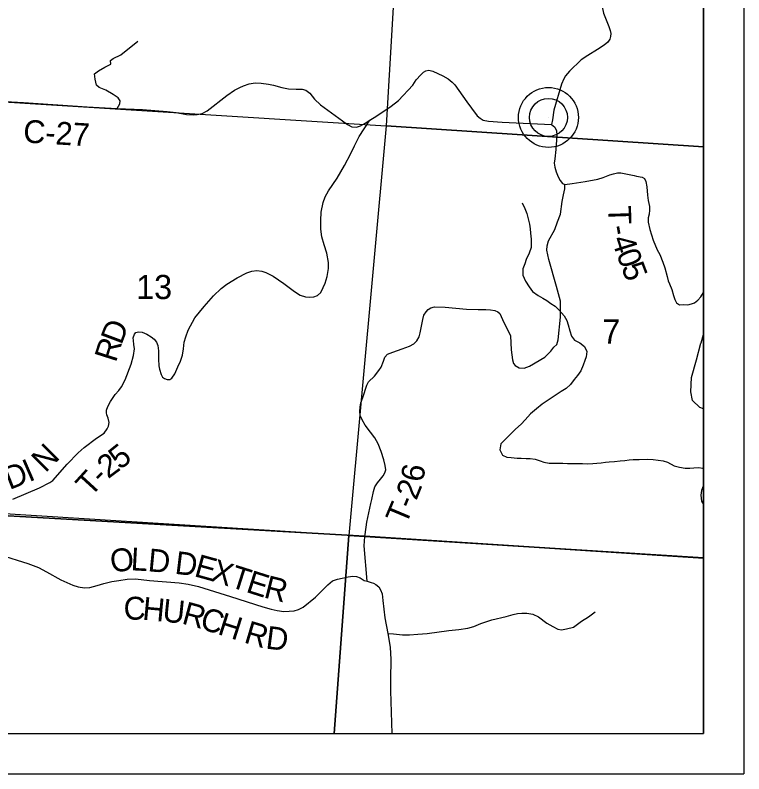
# Model space of a CAD drawing. Extents: x 0 to 34, y 0 to 22.
# Drawn here: x 7.19 to 9, y 14 to 15.883 of the extents above; entities that cross this region are included whole.
import ezdxf

# ---------------------------------------------------------------- set-up
doc = ezdxf.new("R2010")
doc.units = 0
for name, color, linetype in [('GM_X_Corporation', 7, 'Continuous'), ('GM_X_County_Road', 7, 'Continuous'), ('GM_X_County_Road_Text', 7, 'Continuous'), ('GM_X_Major_River', 7, 'Continuous'), ('GM_X_Section_Text', 7, 'Continuous'), ('GM_X_Township_Road', 7, 'Continuous'), ('GM_X_Township_Road_Text', 7, 'Continuous'), ('GM_X_Township_Text', 7, 'Continuous'), ('GM_X_Unincorporated', 7, 'Continuous'), ('GM_X_Unincorporated_Location', 7, 'Continuous'), ('SH_Data', 7, 'Continuous')]:
    doc.layers.add(name, color=color, linetype=linetype)

msp = doc.modelspace()

# ---------------------------------------------------------------- linework, layer by layer
at = {"layer": 'GM_X_Corporation'}
for points in [[(8.9, 15.5562), (8.9, 16.5775), (8.644, 16.594), (8.1703, 16.6232), (8.1663, 16.5368), (8.1403, 16.1), (8.1117, 15.6084)], [(7.097, 15.6707), (7.1079, 15.6712), (8.1117, 15.6084), (8.0192, 14.5919), (7.0183, 14.6543)], [(8.9, 14.5358), (8.9, 15.5562), (8.1117, 15.6084), (8.0192, 14.5919)], [(3.9197, 14.1), (8.9, 14.1), (8.9, 14.5351), (8.0587, 14.59), (7.0121, 14.6499), (6.0453, 14.7107), (5.2037, 14.7544), (4.6148, 14.7919), (3.9742, 14.8327)], [(6.9776, 14.1), (7.9827, 14.1), (8.0192, 14.5919), (7.0183, 14.6543)], [(7.9827, 14.1), (8.9, 14.1), (8.9, 14.5358), (8.0192, 14.5919)]]:
    msp.add_lwpolyline(points, close=True, dxfattribs=at)
at = {"layer": 'GM_X_County_Road'}
for points in [[(8.6428, 16.0121), (8.6415, 15.9944), (8.6407, 15.9598), (8.6432, 15.9369), (8.6456, 15.9158), (8.6518, 15.8883), (8.6643, 15.8553), (8.6681, 15.8451), (8.6695, 15.8379), (8.6687, 15.8305), (8.6671, 15.8238), (8.6624, 15.8161), (8.6534, 15.8085), (8.6369, 15.7985), (8.6126, 15.7832), (8.5958, 15.7721), (8.567, 15.7446), (8.557, 15.7324), (8.5528, 15.7256), (8.547, 15.7123), (8.5284, 15.6477), (8.5247, 15.6238), (8.522, 15.612)], [(7.1364, 15.6707), (7.2111, 15.6666), (7.3687, 15.6558), (7.443, 15.6516), (7.5067, 15.6488), (7.5672, 15.6439), (7.5896, 15.6413), (7.6152, 15.6371), (7.6318, 15.6357), (7.6423, 15.6366), (7.6542, 15.639), (7.6673, 15.6462), (7.7161, 15.6842), (7.7345, 15.6969), (7.7481, 15.7034), (7.7572, 15.7081), (7.771, 15.7125), (7.7861, 15.7151), (7.8013, 15.7144), (7.8195, 15.712), (7.8314, 15.7092), (7.852, 15.7041), (7.8686, 15.7004), (7.8879, 15.6999), (7.9031, 15.6999), (7.9122, 15.6973), (7.9218, 15.6899), (7.9337, 15.6744), (7.9483, 15.6605), (8.0035, 15.621), (8.0154, 15.6119), (8.0264, 15.6065), (8.038, 15.6053), (8.0476, 15.6084), (8.0598, 15.6149), (8.0707, 15.6224), (8.088, 15.6338), (8.1244, 15.6572), (8.1419, 15.6712), (8.1779, 15.7097), (8.1865, 15.7226), (8.1976, 15.7354), (8.2042, 15.7419), (8.21, 15.7453), (8.2175, 15.7464), (8.2274, 15.7442), (8.252, 15.7324), (8.2657, 15.7249), (8.2755, 15.717), (8.2824, 15.71), (8.3117, 15.668), (8.3233, 15.6526), (8.338, 15.6338), (8.3451, 15.6278), (8.3526, 15.6224), (8.3656, 15.6198), (8.3997, 15.6177), (8.522, 15.612)], [(7.1528, 14.5436), (7.2219, 14.5223), (7.248, 14.5125), (7.2679, 14.5018), (7.3033, 14.4817), (7.3332, 14.4682), (7.3468, 14.464), (7.3619, 14.4619), (7.3759, 14.4628), (7.3939, 14.4675), (7.41, 14.4728), (7.4303, 14.477), (7.4474, 14.4803), (7.4686, 14.4829), (7.4889, 14.4838), (7.5235, 14.4803), (7.597, 14.4738), (7.6199, 14.471), (7.6458, 14.4649), (7.7252, 14.4399), (7.8055, 14.4146), (7.8261, 14.4086), (7.8412, 14.4051), (7.8573, 14.4033), (7.8707, 14.4035), (7.883, 14.4047), (7.894, 14.4075), (7.9054, 14.4138), (7.936, 14.4387), (7.9664, 14.4693), (7.9783, 14.4791), (7.9909, 14.4836), (8.0025, 14.4857), (8.017, 14.4894), (8.0285, 14.4908), (8.0376, 14.4899), (8.0471, 14.4864), (8.057, 14.4796), (8.0642, 14.4784), (8.0742, 14.4747), (8.0803, 14.4731), (8.0859, 14.4703), (8.0936, 14.4644), (8.0978, 14.4565), (8.1013, 14.4469), (8.1034, 14.4299), (8.1083, 14.3874), (8.1158, 14.3486), (8.1216, 14.3143), (8.123, 14.2835), (8.1226, 14.2349), (8.1226, 14.206), (8.126, 14.1)]]:
    msp.add_lwpolyline(points, dxfattribs=at)
at = {"layer": 'GM_X_Major_River'}
for points in [[(8.4498, 15.4171), (8.456, 15.4035), (8.4606, 15.391), (8.4644, 15.3774), (8.4675, 15.3641), (8.4691, 15.3531), (8.4699, 15.3418), (8.4718, 15.327), (8.4719, 15.3171), (8.4715, 15.3065), (8.4667, 15.2928), (8.4592, 15.2769), (8.4558, 15.2658), (8.4509, 15.2537), (8.4514, 15.2378), (8.4579, 15.2226), (8.4671, 15.209), (8.4751, 15.1977), (8.4895, 15.1871), (8.5009, 15.1807), (8.5104, 15.1747), (8.5206, 15.1675), (8.5313, 15.1608), (8.5408, 15.1521), (8.5537, 15.1366), (8.5606, 15.1252), (8.5637, 15.1146), (8.5675, 15.0995), (8.5721, 15.0862), (8.5794, 15.0764), (8.5927, 15.0696), (8.6044, 15.061), (8.6098, 15.0481), (8.6087, 15.0352), (8.6054, 15.0257), (8.6012, 15.0143), (8.5952, 15.0006), (8.587, 14.9892), (8.5787, 14.9789), (8.5696, 14.9664), (8.5583, 14.9568), (8.5462, 14.9488), (8.5364, 14.9427), (8.5239, 14.9343), (8.5141, 14.9278), (8.499, 14.9179), (8.4847, 14.9064), (8.4703, 14.8935), (8.4571, 14.8786), (8.4466, 14.8683), (8.4326, 14.8558), (8.4206, 14.8432), (8.4089, 14.8318), (8.396, 14.8192), (8.3935, 14.804), (8.4003, 14.7908), (8.4113, 14.7859), (8.422, 14.7852), (8.4371, 14.7837), (8.4473, 14.7834), (8.4595, 14.7831), (8.4693, 14.7824), (8.4818, 14.7809), (8.494, 14.7772), (8.5034, 14.7734), (8.5167, 14.7712), (8.53, 14.7713), (8.5402, 14.7709), (8.5504, 14.771), (8.5618, 14.7706), (8.5758, 14.7707), (8.5872, 14.77), (8.5993, 14.7701), (8.6106, 14.7697), (8.6247, 14.7702), (8.6345, 14.771), (8.6459, 14.7722), (8.6561, 14.7734), (8.6659, 14.7742), (8.6788, 14.775), (8.6932, 14.7766), (8.7042, 14.7781), (8.7148, 14.7793), (8.725, 14.7801), (8.7401, 14.7806), (8.7602, 14.7807), (8.775, 14.7803), (8.7871, 14.7789), (8.8, 14.7767), (8.8106, 14.7733), (8.8266, 14.7643), (8.8406, 14.7609), (8.8539, 14.7587), (8.866, 14.7588), (8.8762, 14.7592), (8.8879, 14.76), (8.8974, 14.7589), (8.9, 14.7579)], [(8.8995, 14.7164), (8.895, 14.7031), (8.8932, 14.6921), (8.8947, 14.677), (8.9, 14.6689)]]:
    msp.add_lwpolyline(points, dxfattribs=at)
at = {"layer": 'GM_X_Township_Road'}
msp.add_line((8.8936, 15.0701), (8.9, 15.0902), dxfattribs=at)
for points in [[(7.443, 15.6516), (7.4502, 15.6635), (7.4511, 15.6707), (7.4462, 15.6779), (7.4334, 15.6861), (7.4156, 15.6973), (7.3988, 15.7034), (7.3919, 15.7094), (7.3886, 15.7244), (7.3867, 15.7377), (7.3972, 15.7454), (7.4124, 15.7541), (7.4273, 15.7615), (7.4268, 15.7706), (7.4334, 15.776), (7.4521, 15.7846), (7.4948, 15.8185)], [(7.1845, 14.6822), (7.2506, 14.7098), (7.2763, 14.7229), (7.284, 14.7285), (7.3192, 14.7684), (7.3463, 14.7969), (7.3612, 14.8102), (7.3921, 14.8331), (7.4107, 14.8459), (7.4184, 14.8562), (7.4219, 14.863), (7.4233, 14.872), (7.4208, 14.8832), (7.4177, 14.891), (7.4168, 14.8963), (7.417, 14.9029), (7.4198, 14.9117), (7.4266, 14.9241), (7.4383, 14.9418), (7.4472, 14.9519), (7.4539, 14.961), (7.4633, 14.978), (7.4784, 15.017), (7.484, 15.0387), (7.4864, 15.0546), (7.4852, 15.0656), (7.4836, 15.0756), (7.4829, 15.0822), (7.4861, 15.0915), (7.4901, 15.0957), (7.4962, 15.0976), (7.5051, 15.0964), (7.5174, 15.0915), (7.5282, 15.0847), (7.5349, 15.0789), (7.5415, 15.0717), (7.5447, 15.063), (7.5464, 15.0504), (7.5461, 15.0292), (7.5466, 15.0131), (7.5482, 15.0046), (7.5524, 14.9916), (7.5564, 14.985), (7.5613, 14.9811), (7.5676, 14.979), (7.5746, 14.9787), (7.5795, 14.9822), (7.5865, 14.9927), (7.5942, 15.0102), (7.6003, 15.0243), (7.6059, 15.0392), (7.608, 15.0551), (7.6096, 15.0719), (7.6138, 15.0852), (7.6199, 15.1015), (7.6367, 15.1323), (7.6598, 15.1604), (7.6829, 15.1865), (7.7014, 15.2045), (7.7156, 15.2157), (7.7413, 15.2309), (7.7658, 15.2439), (7.7782, 15.2474), (7.7901, 15.2491), (7.8024, 15.2477), (7.813, 15.2442), (7.8305, 15.2358), (7.8576, 15.2173), (7.8835, 15.1977), (7.898, 15.1884), (7.9108, 15.1839), (7.9204, 15.183), (7.9316, 15.1839), (7.9414, 15.1872), (7.9489, 15.1951), (7.9554, 15.2071), (7.9598, 15.218), (7.9654, 15.2346), (7.9682, 15.2542), (7.9682, 15.2696), (7.9638, 15.2923), (7.9577, 15.3135), (7.9517, 15.3334), (7.9493, 15.3523), (7.9489, 15.3737), (7.9498, 15.3943), (7.9549, 15.4183), (7.9603, 15.4326), (7.968, 15.4475), (7.9902, 15.4788), (8.0079, 15.5099), (8.0236, 15.5402), (8.0331, 15.5586), (8.0446, 15.5822), (8.0707, 15.6224)], [(8.522, 15.612), (8.5305, 15.6057), (8.5347, 15.5963), (8.5352, 15.5854), (8.533, 15.5496), (8.5309, 15.5269), (8.529, 15.5162), (8.5309, 15.506), (8.5337, 15.4948), (8.5388, 15.482), (8.5437, 15.4726), (8.5497, 15.4657), (8.5553, 15.4627), (8.5737, 15.4656), (8.6062, 15.4707), (8.6376, 15.4766), (8.6507, 15.4801), (8.6668, 15.4867), (8.6761, 15.4898), (8.686, 15.4916), (8.6946, 15.4916), (8.7279, 15.4852), (8.7337, 15.484)], [(8.7337, 15.484), (8.7471, 15.4814), (8.7534, 15.4777), (8.7568, 15.4706), (8.7588, 15.457), (8.7607, 15.4362), (8.7623, 15.4233), (8.7654, 15.4087), (8.766, 15.399), (8.7647, 15.3893), (8.7623, 15.38), (8.7623, 15.3697), (8.7662, 15.3516), (8.7748, 15.3249), (8.7848, 15.3009), (8.7912, 15.2894), (8.7985, 15.2704), (8.804, 15.2563), (8.8092, 15.2345), (8.8123, 15.2237), (8.8152, 15.2166), (8.8209, 15.2021), (8.8256, 15.1878), (8.8286, 15.1776), (8.8326, 15.169), (8.8403, 15.1646), (8.8498, 15.1648), (8.8606, 15.1646), (8.8699, 15.1664), (8.8771, 15.169), (8.8858, 15.1758), (8.893, 15.1838), (8.8996, 15.195), (8.9, 15.1963)], [(8.0756, 14.6807), (8.0797, 14.7006), (8.0838, 14.7125), (8.0897, 14.7225), (8.0979, 14.7313), (8.1042, 14.7401), (8.1085, 14.7468), (8.1106, 14.7548), (8.1094, 14.7652), (8.1057, 14.7793), (8.0991, 14.8004), (8.0916, 14.8192), (8.0834, 14.8339), (8.0724, 14.8482), (8.0597, 14.8656), (8.0519, 14.8787), (8.0472, 14.8893), (8.0458, 14.8993), (8.0466, 14.9098), (8.0488, 14.921), (8.0535, 14.9339), (8.0636, 14.965), (8.0679, 14.9729), (8.0822, 14.987), (8.0932, 15.0009), (8.0993, 15.0097), (8.1049, 15.0247), (8.1083, 15.0341), (8.1151, 15.0416), (8.1282, 15.0469), (8.1517, 15.0551), (8.1699, 15.0617), (8.1799, 15.0674), (8.1875, 15.0747), (8.1938, 15.0846), (8.1964, 15.0946), (8.1995, 15.1115), (8.2024, 15.1277), (8.2054, 15.1385), (8.2108, 15.1467), (8.2161, 15.1526), (8.2224, 15.1565), (8.2314, 15.159), (8.258, 15.1588), (8.3107, 15.1537), (8.3402, 15.153), (8.3592, 15.1524), (8.3706, 15.152), (8.3811, 15.15), (8.389, 15.1465), (8.3937, 15.1426), (8.4003, 15.1279), (8.4068, 15.1138), (8.4158, 15.0983), (8.4203, 15.0874), (8.4221, 15.0527), (8.4256, 15.0281), (8.4281, 15.0183), (8.4324, 15.0134), (8.442, 15.0077), (8.454, 15.0073), (8.4679, 15.0118), (8.5053, 15.0347), (8.5203, 15.049), (8.5284, 15.0588), (8.5358, 15.0655), (8.5387, 15.077), (8.5444, 15.1338), (8.5442, 15.1737), (8.535, 15.2099), (8.5158, 15.2771), (8.5107, 15.3002), (8.5115, 15.3107), (8.5145, 15.3231), (8.5309, 15.3513), (8.5374, 15.3706), (8.5444, 15.3896), (8.5491, 15.421), (8.552, 15.4374), (8.5556, 15.4525), (8.5553, 15.4627)], [(8.9, 14.906), (8.8908, 14.9095), (8.8721, 14.9267), (8.8681, 14.948), (8.8696, 14.9841), (8.8827, 15.0281), (8.8933, 15.0693), (8.8936, 15.0701)], [(8.0595, 14.5943), (8.0632, 14.6244), (8.0736, 14.6712), (8.0756, 14.6807)], [(8.0642, 14.4784), (8.0572, 14.5657), (8.0589, 14.5895), (8.0595, 14.5943)], [(8.1158, 14.3486), (8.1296, 14.3474), (8.152, 14.3454), (8.1699, 14.3451), (8.1904, 14.3464), (8.2138, 14.3487), (8.2673, 14.3555), (8.2918, 14.3584), (8.3146, 14.3615), (8.3292, 14.3654), (8.3471, 14.3734), (8.3741, 14.3825), (8.4095, 14.3906), (8.4274, 14.3955), (8.4375, 14.3978), (8.4484, 14.3991), (8.4609, 14.3989), (8.4757, 14.396), (8.4903, 14.3893), (8.5105, 14.3742), (8.5256, 14.3654), (8.5382, 14.3589), (8.5474, 14.3571), (8.5599, 14.3597), (8.5765, 14.3643), (8.5968, 14.3789), (8.6139, 14.3898), (8.6311, 14.4023)]]:
    msp.add_lwpolyline(points, dxfattribs=at)
at = {"layer": 'GM_X_Township_Text'}
msp.add_lwpolyline([(3.9742, 14.8327), (4.6148, 14.7919), (5.2037, 14.7544), (6.0453, 14.7107), (7.0121, 14.6499), (8.0587, 14.59), (8.9, 14.5351)], dxfattribs=at)
at = {"layer": 'GM_X_Unincorporated'}
for radius in [0.0744, 0.0472]:
    msp.add_circle((8.5147, 15.6295), radius, dxfattribs=at)
at = {"layer": 'GM_X_Unincorporated_Location'}
msp.add_line((8.5147, 15.6295), (8.5147, 15.6295), dxfattribs=at)
at = {"layer": 'SH_Data'}
for p, q in [((9, 21), (9, 14)), ((8.9, 20.9), (8.9, 14.1)), ((2.1, 14.1), (8.9, 14.1)), ((2, 14), (9, 14))]:
    msp.add_line(p, q, dxfattribs=at)

# ---------------------------------------------------------------- texts
at = {"layer": 'GM_X_County_Road_Text'}
for s, height, rotation, p in [('C-27', 0.05682, 356.5725, (7.2089, 15.5674)), ('O', 0.0568, 6.9971, (7.4293, 14.4994)), ('L', 0.0568, 356.8527, (7.4762, 14.5054)), ('D', 0.0568, 354.575, (7.5181, 14.5031)), ('D', 0.0568, 352.9812, (7.5848, 14.4968)), ('E', 0.0568, 344.5615, (7.6323, 14.4911)), ('X', 0.0568, 342.4532, (7.6727, 14.4799)), ('T', 0.0568, 342.3755, (7.7204, 14.4649)), ('E', 0.0568, 342.457, (7.761, 14.452)), ('R', 0.0568, 346.0516, (7.8053, 14.4381)), ('C', 0.0568, 0.1093, (7.4594, 14.3826)), ('H', 0.0568, 354.6225, (7.5046, 14.3828)), ('U', 0.0568, 354.1357, (7.5543, 14.3781)), ('R', 0.0568, 344.7918, (7.6016, 14.3735)), ('C', 0.0568, 342.4155, (7.646, 14.3614)), ('H', 0.0568, 342.3726, (7.6905, 14.3473)), ('R', 0.0568, 343.4698, (7.756, 14.3265)), ('D', 0.0568, 352.7641, (7.8106, 14.3112))]:
    msp.add_text(s, height=height, rotation=rotation, dxfattribs=at).set_placement(p)
at = {"layer": 'GM_X_Section_Text'}
for s, p in [('13', (7.4906, 15.1785)), ('7', (8.6485, 15.0682))]:
    msp.add_text(s, height=0.06, rotation=0, dxfattribs=at).set_placement(p)
at = {"layer": 'GM_X_Township_Road_Text'}
for s, rotation, p in [('T', 271.7403, (8.6628, 15.4097)), ('-', 279.9619, (8.665, 15.3584)), ('4', 287.3751, (8.671, 15.3276)), ('0', 290.451, (8.6825, 15.2911)), ('5', 290.7884, (8.6948, 15.2579)), ('D', 69.4542, (7.454, 15.063)), ('R', 72.371, (7.4401, 15.0193)), ('N', 44.9908, (7.265, 14.7458)), ('5', 38.4624, (7.4505, 14.7531)), ('2', 36.643, (7.4208, 14.731)), ('D', 21.3985, (7.1758, 14.7043)), ('I', 23.4806, (7.2244, 14.7234)), ('6', 80.3195, (8.203, 14.7221)), ('T', 47.5585, (7.3775, 14.6854)), ('-', 43.8518, (7.4055, 14.716)), ('2', 68.1701, (8.1865, 14.677)), ('T', 67.2499, (8.1607, 14.6153)), ('-', 67.4238, (8.1772, 14.6547))]:
    msp.add_text(s, height=0.0568, rotation=rotation, dxfattribs=at).set_placement(p)

doc.saveas('drawing.dxf')
